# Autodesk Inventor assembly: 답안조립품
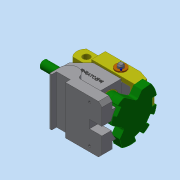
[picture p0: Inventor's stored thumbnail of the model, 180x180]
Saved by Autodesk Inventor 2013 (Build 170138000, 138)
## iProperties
Created: 2016-11
Part Number: 답안조립품
Document SubType Name: Assembly
Designer: Administrator
Author: Administrator
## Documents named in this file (8)
- C:\Users\Administrator\Desktop\461108V1009\답안조립품.iam
- C:\Users\Administrator\Desktop\461108V1009\본체.ipt
- C:\Users\Administrator\Desktop\461108V1009\부시.ipt
- C:\Users\Administrator\Desktop\461108V1009\분할대.ipt
- C:\Users\Administrator\Desktop\461108V1009\분할축.ipt
- C:\Users\Administrator\Desktop\461108V1009\와셔.ipt
- C:\Users\Administrator\Desktop\461108V1009\원통형핀.ipt
- C:\Users\Administrator\Desktop\461108V1009\클레비스핀.ipt
